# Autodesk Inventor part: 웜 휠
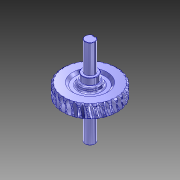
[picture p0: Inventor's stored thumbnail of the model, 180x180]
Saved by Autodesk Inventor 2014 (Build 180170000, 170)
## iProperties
Created: 2013-01
Part Number: 웜 휠
Material: 탄소강
Document SubType Name: Modeling
Designer: 한국산업디자인학원[gmhk.co.kr]
Categories: <?xml version="1.0" encoding="UTF-16"?> <MemberInstance><Categories><FamilyTemplate><FamilyTemplateParameter ValueType="xs:double" Id="1" ObjectReferenceKey="da
Density: 7.87 g/cm^3
Mass: 6988.45 g
Surface Area: 1041.64 cm^2
Volume: 887.987 cm^3
Appearance: _시험-파란색 크롬
CustomPartVersion: 1
Author: 한국산업디자인학원[gmhk.co.kr]
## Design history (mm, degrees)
body "Solid1"
node "톱니 평면"
sketch "기본 본체 스케치"
  geometry: L1 (0, -14)-(0, 14) reference; L2 (0, 20)-(77.639, 20); L3 (77.639, 20)-(82.5, 15.652); L4 (-10, 0)-(60, 0) reference; L5 (82.5, 15.652)-(82.5, -15.652); L6 (0, -20)-(77.639, -20); L7 (0, 20)-(0, -20); L8 (77.639, -20)-(82.5, -15.652); C1 r 20 at (100, 0)
  constraints: 14 end point, 3 symmetric about line, 2 perpendicular, 2 point on line, 1 centre point, 1 collinear
  dimensions: "d50" = 41.8103 deg angle of L3 L2 (= da_fi); "d87" = 165 diameter of L5 L1 (= da_dae); "d89" = 40 diameter of C1 (= 2 x da_aw - da_da); "d92" = 40 distance of L2.start L6.start (= da_b); "d93" = 100 distance from line of C1.centre L7 (= da_aw)
revolve "기본 본체" stored, may be unused: angle "d35" = 90 deg
revolve "기본 본체2" stored, may be unused: angle "d90" = 90 deg
workplane "Work Plane13"
revolve "톱니" stored, may be unused: angle "d43" = 90 deg
pattern_circular "톱니 패턴" dims angle "d46" = 360 deg
workplane "Work Plane14"
workplane "Work Plane15"
revolve "회전6" stored, may be unused: angle "d97" = 90 deg
revolve "회전7" stored, may be unused: angle "d104" = 90 deg
fillet "모깎기1" dims "d105" = 5
chamfer "모따기1" distance "d106" = 1; stored, may be unused: second distance "d107" = 2, angle "d108" = 45 deg
node "작업 평면16"
sketch "스케치11"
  geometry: L1 (-14, 43)-(14, 43) reference; L2 (4, 43)-(4, 22); L3 (-4, 22)-(-4, 43); A1 r 4 centre (0, 22) between (-4, 22) and (4, 22); 2 further points
  constraints: 4 end point, 2 perpendicular, 2 point on circle, 2 point on line, 2 tangent, 1 centre point, 1 midpoint, 1 vertical alignment
  dimensions: "d109" = 8 distance between parallel lines of L2 L3; "d110" = 25 dimension on A1 L1
extrude "돌출1" cut sketch "스케치11" distance "d111" = 4; taper "d112" = 0 deg
mirror "대칭1"
sketch "톱니 스케치"
  geometry: L1 (10, 5.301)-(10, -5.301) reference; L2 (-32.842, 0)-(-12.948, 0) reference; L3 (-90, 6.896)-(-90, -6.896); L4 (-90, -6.896)-(-71, -6.896); L5 (-71, -6.896)-(-59, -2.529); L6 (-59, -2.529)-(-59, 0); L7 (-59, 2.529)-(-71, 6.896); L8 (-71, 6.896)-(-90, 6.896); L9 (-59, 2.529)-(-59, 0); L10 (-65, 0)-(-65, -4.712)
  constraints: 16 end point, 4 perpendicular, 3 equal length, 2 point on line, 1 midpoint, 1 parallel, 1 vertical
  dimensions: "d38" = 100 distance between parallel lines of L1 L3 (= da_aw); "d39" = 20 deg angle of L7 L8 (= da_alfat); "d40" = 19 distance of L7.end L3.start (= 0.5 x da_df1); "d41" = 25 distance between parallel lines of L3 L10 (= 0.5 x da_d1); "d42" = 4.71239 distance of L10.start L10.end (= 0.3 x da_px)
sketch "Sketch8"
  geometry: C1 r 77.639 at (0, 0) reference; C2 r 75 at (0, 0)
  constraints: 1 centre point, 1 coincident
  dimensions: "d77" = 150 diameter of C2 (= da_dw)
body "Srf1"
sketch "스케치9"
  geometry: L1 (-74.283, 20)-(-74.054, 20) reference; L2 (-74.054, 20)-(-74.261, 20) reference; L3 (-74.261, 20)-(-75.727, 20) reference; L4 (-77.355, 20)-(-75.727, 20) reference; L5 (-77.355, 20)-(-77.106, 20) reference; L6 (-77.106, 20)-(-76.222, 20) reference; L7 (-76.222, 20)-(-77.633, 20) reference; L8 (-77.045, 20)-(-77.633, 20) reference; L9 (-77.045, 20)-(-76.789, 20) reference; L10 (-76.789, 20)-(-74.852, 20) reference; L11 (-74.852, 20)-(-76.145, 20) reference; L12 (-73.369, 20)-(-76.145, 20) reference; L13 (-73.369, 20)-(-73.116, 20) reference; L14 (-73.116, 20)-(-70.211, 20) reference; L15 (-70.211, 20)-(-71.33, 20) reference; L16 (-66.486, 20)-(-71.33, 20) reference; L17 (-66.486, 20)-(-66.247, 20) reference; L18 (-66.247, 20)-(-62.501, 20) reference; L19 (-62.501, 20)-(-63.397, 20) reference; L20 (-56.697, 20)-(-63.397, 20) reference; L21 (-56.697, 20)-(-56.483, 20) reference; L22 (-56.483, 20)-(-52.059, 20) reference; L23 (-52.059, 20)-(-52.693, 20) reference; L24 (-44.431, 20)-(-52.693, 20) reference; L25 (-44.431, 20)-(-44.25, 20) reference; L26 (-44.25, 20)-(-39.342, 20) reference; L27 (-39.342, 20)-(-39.687, 20) reference; L28 (-30.222, 20)-(-39.687, 20) reference; L29 (-30.222, 20)-(-30.084, 20) reference; L30 (-30.084, 20)-(-24.906, 20) reference; L31 (-24.906, 20)-(-24.945, 20) reference; L32 (-14.693, 20)-(-24.945, 20) reference; L33 (-14.693, 20)-(-14.602, 20) reference; L34 (-14.602, 20)-(-9.381, 20) reference; L35 (-9.381, 20)-(-9.114, 20) reference; L36 (1.479, 20)-(-9.114, 20) reference; L37 (1.479, 20)-(1.517, 20) reference; L38 (1.517, 20)-(6.554, 20) reference; L39 (6.554, 20)-(7.116, 20) reference; L40 (17.586, 20)-(7.116, 20) reference; L41 (17.586, 20)-(17.571, 20) reference; L42 (17.571, 20)-(22.202, 20) reference; L43 (22.202, 20)-(23.034, 20) reference; L44 (32.924, 20)-(23.034, 20) reference; L45 (32.924, 20)-(32.856, 20) reference; L46 (32.856, 20)-(36.88, 20) reference; L47 (36.88, 20)-(37.946, 20) reference; L48 (46.823, 20)-(37.946, 20) reference; L49 (46.823, 20)-(46.705, 20) reference; L50 (46.705, 20)-(49.946, 20) reference; L51 (49.946, 20)-(51.2, 20) reference; L52 (58.676, 20)-(51.2, 20) reference; L53 (58.676, 20)-(58.514, 20) reference; L54 (58.514, 20)-(60.83, 20) reference; L55 (60.83, 20)-(62.216, 20) reference; L56 (67.965, 20)-(62.216, 20) reference; L57 (67.965, 20)-(67.764, 20) reference; L58 (67.764, 20)-(69.055, 20) reference; L59 (69.055, 20)-(70.512, 20) reference; L60 (74.283, 20)-(70.512, 20) reference; L61 (74.283, 20)-(74.054, 20) reference; L62 (74.054, 20)-(74.261, 20) reference; L63 (74.261, 20)-(75.727, 20) reference; L64 (77.355, 20)-(75.727, 20) reference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
  constraints: 8 end point, 3 point on line, 2 perpendicular, 1 parallel
  dimensions: "d94" = 90 diameter of L122.end L121; "d95" = 135 deg angle of L123 L122; "d96" = 13 distance from line of L121.start L122
node "투영된 루프1"
sketch "스케치10"
  geometry: L1 (45, 13)-(-45, 13) reference; L2 (0, 13)-(0, 133); L3 (0, 133)-(-15, 133); L4 (-15, 133)-(-15, 47); L5 (-15, 47)-(-22.5, 47); L6 (-22.5, 47)-(-22.5, 28); L7 (-22.5, 28)-(-30, 28); L8 (-30, 28)-(-30, 13); L9 (30, 47)-(-30, 47) reference; 1 further point
  constraints: 14 end point, 4 parallel, 3 perpendicular, 1 collinear, 1 midpoint, 1 point on line
  dimensions: "d99" = 30 diameter of L4 L2; "d100" = 45 diameter of L6 L2; "d101" = 60 diameter of L8 L2; "d102" = 15 distance between parallel lines of L7 L1; "d103" = 120 distance of L2.start L2.end
node "참조1"
feature "피치 지름" dims "d78" = 40 (= da_b), "d79" = 0
other parameters: "da_aw" = 100 [user parameter; used in 5 equation terms], "da_fi" = 41.8103 deg [user parameter; used in 1 equation term], "da_b" = 40 [user parameter; used in 2 equation terms], "da_df" = 138 [user parameter], "da_beta" = 1.97396 [user parameter; used in 1 equation term], "da_alfat" = 20 deg [user parameter; used in 1 equation term], "da_df1" = 38 [user parameter; used in 1 equation term], "da_px" = 90 deg [user parameter; used in 1 equation term], "d37" = -1.97396 (computed from da_rightdir, da_beta), "d69" = 0, "d73" = 0, "d75" = 6 deg (computed from da_z), "da_dw" = 150 [user parameter; used in 1 equation term], "da_rightdir" = 0 [user parameter; used in 1 equation term], "d80" = 0, "d81" = 0, "d82" = 0, "d83" = 6 deg (computed from da_z), "d84" = 0, "d85" = 180 deg, "da_dae" = 165 [user parameter; used in 1 equation term]
